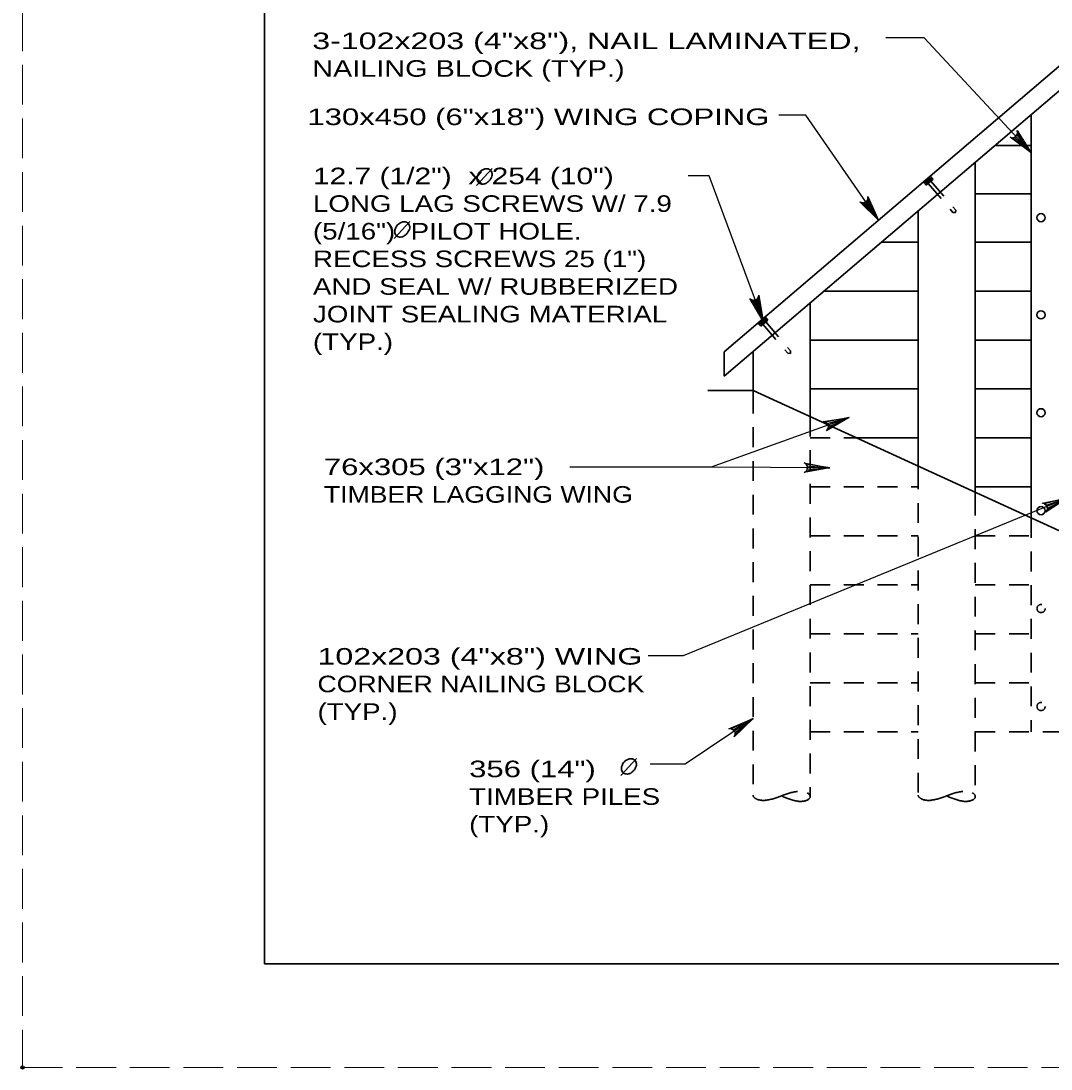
# Model space of a CAD drawing. Extents: x -6.4 to 73.1, y -66 to 0.
# Drawn here: x -0.01 to 7.44, y -66.01 to -58.43 of the extents above; entities that cross this region are included whole.
import ezdxf

# ---------------------------------------------------------------- set-up
doc = ezdxf.new("R2010")
doc.units = 0
doc.header["$LTSCALE"] = 0.048
doc.header["$PDMODE"] = 32
doc.header["$PDSIZE"] = 0.024
doc.linetypes.add('LONG_DASHED', pattern=[7.5, 6, -1.5])
doc.linetypes.add('MEDIUM_DASHED', pattern=[4.5, 3, -1.5])
for name, color, linetype, lineweight in [('1', 7, 'Continuous', 13), ('4', 7, 'Continuous', 25), ('5', 7, 'Continuous', 25), ('63', 7, 'LONG_DASHED', 13)]:
    doc.layers.add(name, color=color, linetype=linetype, lineweight=lineweight)
doc.layers.add('62', color=7, linetype='Continuous')

msp = doc.modelspace()

# ---------------------------------------------------------------- hatches: boundary and pattern name
at = {"layer": '5'}
for points in [[(7.29858, -59.38017), (7.22525, -59.28708), (7.21083, -59.3005)], [(5.18067, -63.52208), (5.20175, -63.55342), (5.28525, -63.47442)]]:
    msp.add_hatch(color=256, dxfattribs=at).paths.add_polyline_path(points)

# ---------------------------------------------------------------- linework, layer by layer
at = {"layer": '1', "lineweight": 35}
msp.add_lwpolyline([(1.75, -65.25), (33.25, -65.25), (33.25, -44.75), (1.75, -44.75)], close=True, dxfattribs=at)
at = {"layer": '4', "lineweight": 35}
for p, q in [((7.53217, -58.72783), (5.07708, -60.82092)), ((7.53217, -58.905), (5.07708, -60.99808)), ((7.29858, -59.10417), (7.29858, -62.02258)), ((7.0355, -59.32842), (7.29858, -59.32842)), ((6.894, -59.44908), (6.894, -61.86125)), ((6.53733, -59.61508), (6.518, -59.59242)), ((6.58842, -59.57158), (6.53733, -59.61508)), ((6.5465, -59.60733), (6.53858, -59.598)), ((6.56483, -59.57067), (6.54025, -59.59167)), ((6.5465, -59.60733), (6.579, -59.57967)), ((6.547, -59.59083), (6.55492, -59.60017)), ((6.56325, -59.577), (6.57117, -59.58633)), ((6.58842, -59.57158), (6.56908, -59.54892)), ((6.579, -59.57967), (6.57108, -59.57033)), ((6.894, -59.67775), (7.29858, -59.67775)), ((6.48058, -59.8015), (6.48058, -61.67158)), ((6.751, -59.81317), (6.75192, -59.79517)), ((6.21608, -60.027), (6.48058, -60.027)), ((6.894, -60.027), (7.29858, -60.027)), ((5.8005, -60.38133), (6.48058, -60.38133)), ((6.894, -60.38133), (7.29858, -60.38133)), ((5.69867, -60.46817), (5.69867, -61.28883)), ((5.39308, -60.59067), (5.342, -60.63417)), ((5.3695, -60.58975), (5.34492, -60.61075)), ((5.35117, -60.62642), (5.38367, -60.59875)), ((5.36792, -60.59608), (5.37583, -60.60542)), ((5.39308, -60.59067), (5.37375, -60.568)), ((5.38367, -60.59875), (5.37575, -60.58942)), ((5.342, -60.63417), (5.32275, -60.61158)), ((5.35117, -60.62642), (5.34325, -60.61708)), ((5.35167, -60.60992), (5.35958, -60.61925)), ((5.69867, -60.73567), (6.48058, -60.73567)), ((6.894, -60.73567), (7.29858, -60.73567)), ((5.07708, -60.82092), (5.07708, -60.99808)), ((5.28525, -60.82058), (5.28525, -61.12608)), ((4.95792, -61.09975), (5.28525, -61.09975)), ((5.2865, -61.09975), (7.80325, -62.25408)), ((5.69867, -61.09), (6.48058, -61.09)), ((6.894, -61.09), (7.29858, -61.09)), ((6.03775, -61.44433), (6.48058, -61.44433)), ((6.894, -61.44433), (7.29858, -61.44433)), ((6.894, -61.79867), (7.29858, -61.79867))]:
    msp.add_line(p, q, dxfattribs=at)
at = {"layer": '4', "linetype": 'MEDIUM_DASHED', "lineweight": 35}
for p, q in [((6.57275, -59.58492), (6.75192, -59.79517)), ((5.37742, -60.604), (5.55667, -60.81425)), ((5.28525, -61.12333), (5.28525, -64.02908)), ((5.69867, -61.28883), (5.69867, -64.04017)), ((5.69867, -61.44433), (6.03775, -61.44433)), ((6.48058, -61.67158), (6.48058, -64.02908)), ((5.69867, -61.79867), (6.48058, -61.79867)), ((6.894, -61.86125), (6.894, -64.04017)), ((7.29858, -62.02258), (7.29858, -63.57033)), ((5.69867, -62.153), (6.48058, -62.153)), ((6.894, -62.153), (7.29858, -62.153)), ((5.69867, -62.50733), (6.48058, -62.50733)), ((6.894, -62.50733), (7.29858, -62.50733)), ((5.69867, -62.86167), (6.48058, -62.86167)), ((6.894, -62.86167), (7.29858, -62.86167)), ((5.69867, -63.216), (6.48058, -63.216)), ((6.894, -63.216), (7.29858, -63.216)), ((5.69867, -63.57033), (6.48058, -63.57033)), ((6.894, -63.57033), (7.68092, -63.57033))]:
    msp.add_line(p, q, dxfattribs=at)
for points in [[(6.55275, -59.602), (6.732, -59.81217), (6.751, -59.81317)], [(5.35742, -60.62108), (5.53667, -60.83125), (5.55575, -60.83225), (5.55667, -60.81425)]]:
    msp.add_lwpolyline(points, dxfattribs=at)
at = {"layer": '4', "lineweight": 35}
for centre in [(7.36978, -59.84965), (7.36978, -60.55329), (7.36978, -61.26195), (7.36978, -61.97061)]:
    msp.add_circle(centre, 0.02953, dxfattribs=at)
at = {"layer": '4', "linetype": 'MEDIUM_DASHED', "lineweight": 35}
for centre in [(7.36978, -62.67927), (7.36978, -63.38793)]:
    msp.add_circle(centre, 0.02953, dxfattribs=at)
at = {"layer": '4', "lineweight": 35}
for centre, radius, start, end in [((6.5442, -59.59607), 0.00592, 128.62254, 199.16266), ((6.5442, -59.59607), 0.00592, 61.73655, 128.62254), ((6.56368, -59.59397), 0.01696, 91.4996, 169.39961), ((6.56819, -59.57491), 0.00539, 57.90141, 202.9978), ((5.34887, -60.61516), 0.00592, 61.73655, 128.62254), ((5.36835, -60.61306), 0.01696, 91.4996, 169.39961), ((5.37286, -60.594), 0.00539, 57.90141, 202.9978), ((5.34887, -60.61516), 0.00592, 128.62254, 199.16266)]:
    msp.add_arc(centre, radius, start, end, dxfattribs=at)
at = {"layer": '4', "linetype": 'MEDIUM_DASHED', "lineweight": 35}
for centre, major_axis, start_param, end_param in [((5.69593, -64.14352), (0.29233, -0.00784), 1.8903203, 2.3561945), ((5.62547, -64.0382), (0.07323, -0.00196), 4.4555879, 8.1107827), ((6.89126, -64.14352), (0.29233, -0.00784), 1.8903203, 2.3561945), ((6.82081, -64.0382), (0.07323, -0.00196), 4.4555879, 8.1107827), ((5.35851, -64.03105), (-0.07323, 0.00196), 6.2831853, 8.1107827), ((5.28805, -63.92573), (-0.29233, 0.00784), 1.8903203, 2.3561945), ((5.70147, -63.93681), (0.29233, -0.00784), 3.9269908, 4.392865), ((6.55384, -64.03105), (-0.07323, 0.00196), 6.2831853, 8.1107827), ((6.48339, -63.92573), (-0.29233, 0.00784), 1.8903203, 2.3561945), ((6.8968, -63.93681), (0.29233, -0.00784), 3.9269908, 4.392865)]:
    msp.add_ellipse(centre, major_axis=major_axis, ratio=0.5, start_param=start_param, end_param=end_param, dxfattribs=at)
at = {"layer": '4'}
for p in [(6.54175, -59.59067), (6.54217, -59.59025), (6.54267, -59.58983), (6.54308, -59.5895), (6.54325, -59.59008), (6.5435, -59.58908), (6.54367, -59.58975), (6.544, -59.58867), (6.54417, -59.58933), (6.54433, -59.59), (6.54442, -59.58833), (6.54458, -59.589), (6.54475, -59.58958), (6.54492, -59.58792), (6.545, -59.58858), (6.54525, -59.58925), (6.54533, -59.58758), (6.54542, -59.58983), (6.5455, -59.58817), (6.54567, -59.58883), (6.54575, -59.58717), (6.54583, -59.5895), (6.54592, -59.58783), (6.546, -59.59008), (6.54608, -59.5885), (6.54625, -59.58675), (6.54625, -59.58908), (6.54642, -59.58742), (6.54642, -59.58975), (6.54658, -59.58808), (6.54658, -59.59042), (6.54667, -59.58642), (6.54675, -59.58875), (6.54683, -59.58708), (6.54683, -59.58933), (6.547, -59.58767), (6.547, -59.59), (6.54708, -59.586), (6.54717, -59.58833), (6.54733, -59.58667), (6.54733, -59.589), (6.5475, -59.58733), (6.54758, -59.58567), (6.54758, -59.588), (6.54775, -59.58625), (6.54792, -59.58692), (6.548, -59.58525), (6.54817, -59.58592), (6.54833, -59.58658), (6.5485, -59.58483), (6.54867, -59.5855), (6.54892, -59.5845), (6.54908, -59.58517), (6.54942, -59.58408), (6.54983, -59.58375), (6.55025, -59.58333), (6.55075, -59.583), (6.55475, -59.5795), (6.55525, -59.57908), (6.55567, -59.57875), (6.55608, -59.57833), (6.55658, -59.578), (6.557, -59.57758), (6.55717, -59.57825), (6.5575, -59.57717), (6.55767, -59.57783), (6.55792, -59.57683), (6.55808, -59.5775), (6.55833, -59.57642), (6.5585, -59.57708), (6.55867, -59.57775), (6.55883, -59.57608), (6.559, -59.57675), (6.55917, -59.57733), (6.55925, -59.57567), (6.55942, -59.57633), (6.55958, -59.577), (6.55967, -59.57533), (6.55992, -59.57592), (6.56008, -59.57658), (6.56017, -59.57492), (6.56017, -59.57725), (6.56033, -59.57558), (6.5605, -59.57617), (6.56058, -59.5745), (6.56067, -59.57683), (6.56075, -59.57517), (6.56092, -59.57583), (6.56108, -59.5765), (6.56117, -59.57408), (6.56125, -59.57483), (6.56125, -59.57708), (6.56133, -59.57475), (6.56142, -59.57542), (6.5615, -59.57608), (6.56158, -59.57367), (6.56167, -59.57667), (6.56175, -59.57433), (6.56192, -59.575), (6.562, -59.57567), (6.56208, -59.57333), (6.56208, -59.57567), (6.56217, -59.574), (6.56217, -59.57633), (6.56233, -59.57458), (6.56233, -59.577), (6.5625, -59.57292), (6.5625, -59.57525), (6.56267, -59.57358), (6.56267, -59.57592), (6.56275, -59.57658), (6.56283, -59.57425), (6.56283, -59.5765), (6.56292, -59.57258), (6.56308, -59.57317), (6.56342, -59.57217), (6.56383, -59.57175), (5.34642, -60.60975), (5.34683, -60.60933), (5.34733, -60.60892), (5.34775, -60.60858), (5.34792, -60.60925), (5.34817, -60.60817), (5.34833, -60.60883), (5.34867, -60.60783), (5.34883, -60.60842), (5.349, -60.60908), (5.34908, -60.60742), (5.34925, -60.60808), (5.34942, -60.60867), (5.34958, -60.607), (5.34975, -60.60767), (5.34992, -60.60833), (5.35, -60.60667), (5.35008, -60.60892), (5.35017, -60.60725), (5.35033, -60.60792), (5.35042, -60.60625), (5.3505, -60.60858), (5.35067, -60.60692), (5.35067, -60.60917), (5.35075, -60.60758), (5.35092, -60.60583), (5.35092, -60.60817), (5.35108, -60.6065), (5.35108, -60.60883), (5.35125, -60.60717), (5.35125, -60.6095), (5.35133, -60.6055), (5.35142, -60.60783), (5.3515, -60.60617), (5.3515, -60.60842), (5.35167, -60.60675), (5.35167, -60.60908), (5.35183, -60.60508), (5.35183, -60.60742), (5.352, -60.60575), (5.352, -60.60808), (5.35217, -60.60642), (5.35225, -60.60475), (5.35225, -60.60708), (5.35242, -60.60533), (5.35258, -60.606), (5.35267, -60.60433), (5.35283, -60.605), (5.353, -60.60567), (5.35317, -60.60392), (5.35333, -60.60458), (5.35358, -60.60358), (5.35375, -60.60425), (5.35408, -60.60317), (5.3545, -60.60283), (5.35492, -60.60242), (5.35542, -60.60208), (5.35942, -60.59858), (5.35992, -60.59825), (5.36033, -60.59783), (5.36075, -60.59742), (5.36125, -60.59708), (5.36167, -60.59667), (5.36183, -60.59733), (5.36217, -60.59625), (5.36233, -60.59692), (5.36258, -60.59592), (5.36275, -60.59658), (5.363, -60.5955), (5.36325, -60.59617), (5.36333, -60.59683), (5.3635, -60.59517), (5.36367, -60.59583), (5.36383, -60.59642), (5.36392, -60.59475), (5.36408, -60.59542), (5.36425, -60.59608), (5.36442, -60.59442), (5.36458, -60.595), (5.36475, -60.59567), (5.36483, -60.594), (5.36483, -60.59633), (5.365, -60.59467), (5.36517, -60.59533), (5.36525, -60.59358), (5.36533, -60.59592), (5.36542, -60.59425), (5.36558, -60.59492), (5.36575, -60.59558), (5.36583, -60.59317), (5.36592, -60.59392), (5.36592, -60.59617), (5.366, -60.59383), (5.36608, -60.5945), (5.36625, -60.59275), (5.36625, -60.59517), (5.36633, -60.59583), (5.36642, -60.59342), (5.36658, -60.59408), (5.36667, -60.59483), (5.36675, -60.59242), (5.36675, -60.59475), (5.36683, -60.59308), (5.36683, -60.59542), (5.367, -60.59367), (5.367, -60.59608), (5.36717, -60.592), (5.36717, -60.59433), (5.36733, -60.59267), (5.36733, -60.595), (5.36742, -60.59567), (5.3675, -60.59333), (5.3675, -60.59558), (5.36758, -60.59167), (5.36775, -60.59225), (5.36808, -60.59125), (5.3685, -60.59083)]:
    msp.add_point(p, dxfattribs=at)
at = {"layer": '5'}
for p, q in [((6.52333, -58.54875), (6.24583, -58.54875)), ((7.29858, -59.38017), (6.52333, -58.54875)), ((5.98108, -61.29583), (4.98158, -61.65567)), ((4.98158, -61.65567), (3.95933, -61.65567)), ((5.842, -61.65967), (4.98158, -61.65567)), ((7.56275, -61.87892), (4.78075, -63.02125)), ((4.78075, -63.02125), (4.52767, -63.02125))]:
    msp.add_line(p, q, dxfattribs=at)
at = {"layer": '5', "lineweight": 35}
for p, q in [((3.2855, -59.61708), (3.3975, -59.4945)), ((2.689, -60.00092), (2.801, -59.87825)), ((4.32975, -63.88725), (4.44175, -63.76458))]:
    msp.add_line(p, q, dxfattribs=at)
at = {"layer": '5'}
for points in [[(6.1935, -59.86908), (5.66692, -59.109), (5.4725, -59.109)], [(7.29858, -59.38017), (7.14592, -59.26767), (7.163, -59.27142), (7.17717, -59.26825), (7.18775, -59.26133), (7.19542, -59.25125), (7.1995, -59.23725), (7.197, -59.22), (7.29858, -59.38017), (7.1995, -59.23725), (7.19542, -59.25125), (7.29858, -59.38017), (7.18775, -59.26133), (7.17717, -59.26825), (7.29858, -59.38017), (7.163, -59.27142)], [(5.35967, -60.59817), (4.96825, -59.54625), (4.81717, -59.54625)], [(6.1935, -59.86908), (6.05867, -59.73575), (6.06683, -59.73883), (6.075, -59.74192), (6.08225, -59.74142), (6.0895, -59.74092), (6.09525, -59.73825), (6.101, -59.7355), (6.1055, -59.73108), (6.11, -59.72667), (6.11308, -59.72008), (6.11608, -59.71342), (6.11608, -59.70475), (6.11608, -59.696), (6.1935, -59.86908), (6.11608, -59.70475), (6.11608, -59.71342), (6.1935, -59.86908), (6.11308, -59.72008), (6.11, -59.72667), (6.1935, -59.86908), (6.1055, -59.73108), (6.101, -59.7355), (6.1935, -59.86908), (6.09525, -59.73825), (6.0895, -59.74092), (6.1935, -59.86908), (6.08225, -59.74142), (6.075, -59.74192), (6.1935, -59.86908), (6.06683, -59.73883)], [(5.35967, -60.59817), (5.26183, -60.43567), (5.269, -60.44067), (5.27617, -60.44567), (5.28333, -60.44692), (5.2905, -60.44825), (5.29675, -60.44708), (5.303, -60.44592), (5.30842, -60.44275), (5.31392, -60.4395), (5.3185, -60.43392), (5.32308, -60.42825), (5.32525, -60.41975), (5.32742, -60.41133), (5.35967, -60.59817), (5.32525, -60.41975), (5.32308, -60.42825), (5.35967, -60.59817), (5.3185, -60.43392), (5.31392, -60.4395), (5.35967, -60.59817), (5.30842, -60.44275), (5.303, -60.44592), (5.35967, -60.59817), (5.29675, -60.44708), (5.2905, -60.44825), (5.35967, -60.59817), (5.28333, -60.44692), (5.27617, -60.44567), (5.35967, -60.59817), (5.269, -60.44067)], [(5.98108, -61.29583), (5.8175, -61.39183), (5.82767, -61.37767), (5.83042, -61.36333), (5.82817, -61.35092), (5.82192, -61.33983), (5.81075, -61.33058), (5.79383, -61.32608), (5.98108, -61.29583), (5.81075, -61.33058), (5.82192, -61.33983), (5.98108, -61.29583), (5.82817, -61.35092), (5.83042, -61.36333), (5.98108, -61.29583), (5.82767, -61.37767)], [(5.842, -61.65967), (5.65542, -61.69375), (5.66983, -61.68383), (5.67733, -61.67142), (5.6795, -61.65892), (5.67742, -61.64642), (5.67008, -61.63383), (5.65575, -61.62383), (5.842, -61.65967), (5.67008, -61.63383), (5.67742, -61.64642), (5.842, -61.65967), (5.6795, -61.65892), (5.67733, -61.67142), (5.842, -61.65967), (5.66983, -61.68383)], [(7.56275, -61.87892), (7.40358, -61.98208), (7.41308, -61.96742), (7.41517, -61.953), (7.41242, -61.94067), (7.40567, -61.92992), (7.39408, -61.92117), (7.377, -61.91742), (7.56275, -61.87892), (7.39408, -61.92117), (7.40567, -61.92992), (7.56275, -61.87892), (7.41242, -61.94067), (7.41517, -61.953), (7.56275, -61.87892), (7.41308, -61.96742)], [(5.28525, -63.47442), (4.79325, -63.8055), (4.54183, -63.8055)], [(5.28525, -63.47442), (5.15008, -63.6075), (5.1565, -63.59125), (5.15567, -63.57667), (5.15042, -63.56517), (5.14167, -63.556), (5.12858, -63.54975), (5.11108, -63.5495), (5.28525, -63.47442), (5.12858, -63.54975), (5.14167, -63.556), (5.28525, -63.47442), (5.15042, -63.56517), (5.15567, -63.57667), (5.28525, -63.47442), (5.1565, -63.59125)]]:
    msp.add_lwpolyline(points, dxfattribs=at)
for points in [[(7.29858, -59.38017), (7.22525, -59.28708), (7.21083, -59.3005)], [(5.18067, -63.52208), (5.20175, -63.55342), (5.28525, -63.47442)]]:
    msp.add_lwpolyline(points, close=True, dxfattribs=at)
at = {"layer": '5', "lineweight": 35}
for points in [[(3.38583, -59.50658), (3.37708, -59.49975), (3.36833, -59.49733), (3.35733, -59.49633), (3.35108, -59.49633), (3.34033, -59.49883), (3.3305, -59.50333), (3.32358, -59.50725), (3.31033, -59.51783), (3.3, -59.53133), (3.29375, -59.544), (3.29008, -59.55558), (3.289, -59.56633), (3.29008, -59.57558), (3.29458, -59.58875), (3.29933, -59.59558), (3.309, -59.60283), (3.3235, -59.60633), (3.34, -59.60583), (3.36083, -59.59633), (3.37608, -59.58325), (3.38758, -59.56733), (3.39508, -59.55075), (3.39758, -59.53233), (3.39433, -59.5205), (3.38633, -59.50658)], [(2.78933, -59.89042), (2.78058, -59.8835), (2.77183, -59.88117), (2.76083, -59.88017), (2.75458, -59.88017), (2.74383, -59.88267), (2.734, -59.88717), (2.72708, -59.891), (2.71383, -59.90167), (2.7035, -59.91517), (2.69725, -59.92775), (2.69358, -59.93942), (2.6925, -59.95017), (2.69358, -59.95942), (2.69808, -59.9725), (2.70283, -59.97942), (2.7125, -59.98667), (2.727, -59.99017), (2.7435, -59.98967), (2.76433, -59.98017), (2.77958, -59.967), (2.79108, -59.95117), (2.79858, -59.9345), (2.80108, -59.91617), (2.79783, -59.90425), (2.78983, -59.89042)], [(4.43008, -63.77675), (4.42133, -63.76983), (4.41258, -63.7675), (4.40158, -63.7665), (4.39533, -63.7665), (4.38458, -63.769), (4.37475, -63.7735), (4.36783, -63.77733), (4.35458, -63.788), (4.34425, -63.8015), (4.338, -63.81408), (4.33433, -63.82575), (4.33325, -63.8365), (4.33433, -63.84575), (4.33883, -63.85883), (4.34358, -63.86575), (4.35325, -63.873), (4.36775, -63.8765), (4.38425, -63.876), (4.40508, -63.8665), (4.42033, -63.85333), (4.43183, -63.8375), (4.43933, -63.82083), (4.44183, -63.8025), (4.43858, -63.79058), (4.43058, -63.77675)]]:
    msp.add_spline(points, degree=3, dxfattribs=at)
at = {"layer": '62'}
msp.add_point((0, -66), dxfattribs=at)
at = {"layer": '63'}
msp.add_lwpolyline([(0, -66), (34, -66), (34, -44), (0, -44)], close=True, dxfattribs=at)

# ---------------------------------------------------------------- texts
at = {"layer": '5'}
for s, width, p in [('3-102x203 (4"x8"), NAIL LAMINATED,', 1.45, (2.09567, -58.63017)), ('NAILING BLOCK (TYP.)', 1.3, (2.09567, -58.83017)), ('130x450 (6"x18") WING COPING', 1.4, (2.06083, -59.17992)), ('12.7 (1/2")  x 254 (10")', 1.35, (2.10092, -59.60808)), ('LONG LAG SCREWS W/ 7.9', 1.25, (2.10092, -59.80808)), ('(5/16")  PILOT HOLE.', 1.25, (2.10092, -60.00808)), ('RECESS SCREWS 25 (1")', 1.25, (2.10092, -60.20808)), ('AND SEAL W/ RUBBERIZED', 1.25, (2.10092, -60.40808)), ('JOINT SEALING MATERIAL', 1.25, (2.10092, -60.60808)), ('(TYP.)', 1.25, (2.10092, -60.80808)), ('76x305 (3"x12")', 1.4, (2.17992, -61.71325)), ('TIMBER LAGGING WING', 1.2, (2.17992, -61.91325)), ('102x203 (4"x8") WING', 1.45, (2.13375, -63.085)), ('CORNER NAILING BLOCK', 1.2, (2.13375, -63.285)), ('(TYP.)', 1.25, (2.13375, -63.485)), ('356 (14") ', 1.4, (3.23125, -63.89983)), ('TIMBER PILES', 1.25, (3.23125, -64.09983)), ('(TYP.)', 1.25, (3.23125, -64.29983))]:
    msp.add_text(s, height=0.12, dxfattribs=dict(at, width=width)).set_placement(p)

doc.saveas('drawing.dxf')
